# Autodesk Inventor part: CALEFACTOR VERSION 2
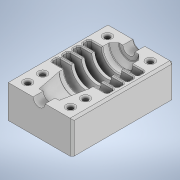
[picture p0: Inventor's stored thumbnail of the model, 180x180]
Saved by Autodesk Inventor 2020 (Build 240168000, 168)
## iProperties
Created: 2022-10
Part Number: CALEFACTOR VERSION 2
Material: Genérico
Document SubType Name: Modeling
Designer: SEBAS
Density: 1 g/cm^3
Appearance: Valor por defecto
Author: SEBAS
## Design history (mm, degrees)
sketch "Boceto1"
  geometry: L1 (0, 0)-(0, 102); L2 (0, 102)-(33, 102); L3 (0, 0)-(33, 0); L4 (33, 0)-(33, 12); L5 (33, 12)-(23, 12); L6 (18, 17)-(18, 24); L7 (18, 67)-(18, 62); L8 (18, 17)-(23, 12); L9 (18, 24)-(5, 24); L10 (5, 24)-(5, 31.25); L11 (5, 31.25)-(18, 31.25); L12 (18, 31.25)-(18, 34.25); L13 (18, 34.25)-(5, 34.25); L14 (5, 34.25)-(5, 41.5); L15 (5, 41.5)-(18, 41.5); L16 (18, 41.5)-(18, 44.5); L17 (18, 44.5)-(5, 44.5); L18 (5, 44.5)-(5, 51.75); L19 (5, 51.75)-(18, 51.75); L20 (18, 62)-(5, 62); L21 (5, 62)-(5, 54.75); L22 (5, 54.75)-(18, 54.75); L23 (18, 54.75)-(18, 51.75); L24 (18, 67)-(23, 92); L25 (33, 102)-(33, 92); L26 (33, 92)-(23, 92); L27 (18, 17)-(18, 7.5); L28 (33, 102)-(33, 0)
  constraints: 57 end point, 12 perpendicular, 6 horizontal alignment, 6 vertical, 6 vertical alignment, 5 collinear, 5 horizontal, 5 point on line
  dimensions: "d0" = 102 distance of L1.start L1.end; "d1" = 33 distance of L1.end L2.end; "d6" = 5 distance of L7.start L7.end; "d7" = 7 distance of L6.start L6.end; "d12" = 3 distance of L11.end L12.end; "d14" = 13 distance of L7.end L20.end; "d15" = 25 vertical distance of L7.start L24.end; "d16" = 5 horizontal distance of L7.start L24.end; "d17" = 45 deg angle of L27 L8; "d18" = 38 distance of L9.end L20.end; "d20" = 10 distance of L2.end L25.end; "d21" = 5 distance between parallel lines of L1 L21
revolve "Revolución1" sketch "Boceto1" stored, may be unused: angle "d22" = 180 deg
sketch "Boceto2"
  geometry: L1 (-33, -33)-(33, -33); L2 (-33, -33)-(-33, 0); L3 (-33, 0)-(33, 0); L4 (33, 0)-(33, -33); A1 r 33 centre (0, 0) between (-33, 0) and (33, 0) reference; 2 further points
  constraints: 8 end point, 2 perpendicular, 1 horizontal, 1 midpoint, 1 point on circle, 1 tangent, 1 vertical, 1 vertical alignment
extrude "Extrusión1" join sketch "Boceto2" stored distance "d23" = 10; taper "d24" = 0 deg
sketch "Boceto3"
  geometry: L1 (23, 33)-(43, 33) reference; C1 r 6 at (33, 33); 1 further point
  constraints: 1 centre point, 1 midpoint
  dimensions: "d25" = 12 diameter of C1
extrude "Extrusión2" cut sketch "Boceto3" stored distance "d26" = 10; taper "d27" = 0 deg
fillet "Empalme2" dims "d29" = 2
chamfer "Chaflán1" distance "d30" = 2; stored, may be unused: second distance "d31" = 2, angle "d32" = 45 deg
fillet "Empalme3" dims "d33" = 1
sketch "Boceto4"
  geometry: L1 (-15.5, 90)-(27.5, 90); C1 r 2.5 at (-15.5, 90); C2 r 2.5 at (27.5, 90); C3 r 2.5 at (-15.5, 10); C4 r 2.5 at (27.5, 10); C5 r 2.5 at (-15.5, 25); C6 r 2.5 at (27.5, 25); 2 further points
  constraints: 6 centre point, 5 equal radius, 5 vertical alignment, 2 end point, 2 horizontal alignment, 1 horizontal, 1 midpoint
  dimensions: "d34" = 43 distance of L1.start L1.end; "d35" = 5 diameter of C2; "d36" = 12 distance of point (6, 102) point (6, 90); "d37" = 77 vertical distance of C6.centre point (6, 102); "d38" = 15 distance of C4.centre C6.centre
extrude "Extrusión3" cut sketch "Boceto4" distance "d39" = 15; taper "d40" = 0 deg
fillet "Empalme4" dims "d41" = 2
node "Sólido1"
